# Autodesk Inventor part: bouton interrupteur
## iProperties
Author: Administrateur
Created: 2001-04
Part Number: bouton interrupteur
Material: Par défaut
Document SubType Name: Modélisation
Designer: Administrateur
Control State: 0
Master: False
Checked Out: False
PropertySet Name: Design Tracking Control
Shininess: 20.0
PropertySet Name: _Private Model Information
Length Units: 11269
Angle Units: 11283
Time Units: 11279
Mass Units: 11290
Length Display Precision: 3
Angle Display Precision: 2
Compacted: False
Density: 0.0
Volumn: 0.0
Area: 0.0
PropertySet Name: Model Information
